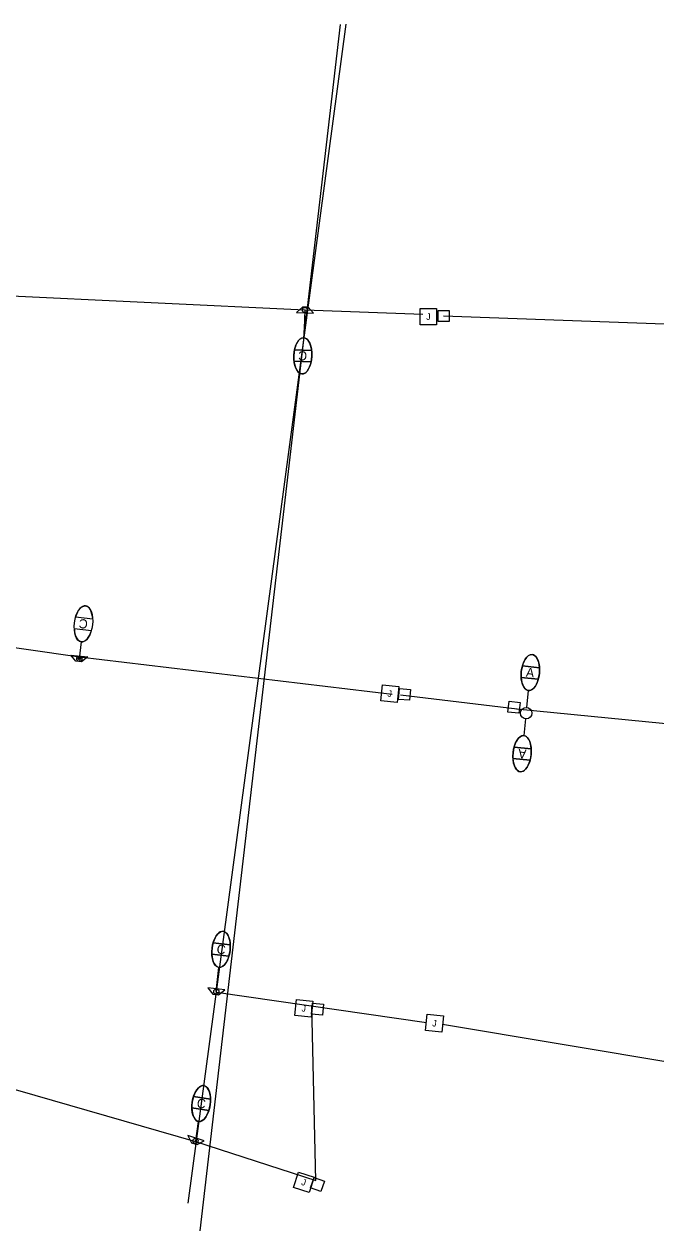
# Model space of a CAD drawing. Extents: x 915723 to 927758, y 636394 to 638609.
# Drawn here: x 926458 to 926734, y 636503 to 637030 of the extents above; entities that cross this region are included whole.
import ezdxf

# ---------------------------------------------------------------- set-up
doc = ezdxf.new("R2010")
doc.units = 0
for name, color, linetype in [('ConduitBM', 7, 'Continuous'), ('ConduitOT', 7, 'Continuous'), ('DrShaftConc', 7, 'Continuous'), ('Masonry_h', 7, 'Continuous'), ('Miscellaneous2', 7, 'Continuous'), ('PoleLight', 7, 'Continuous'), ('PullBox', 7, 'Continuous'), ('TextStructuresLabel', 7, 'Continuous')]:
    doc.layers.add(name, color=color, linetype=linetype)

msp = doc.modelspace()

# ---------------------------------------------------------------- linework, layer by layer
at = {"layer": 'ConduitBM'}
for p, q in [((926580.52, 636905.43), (926370.11, 636915.42)), ((926632.01, 636903.45), (926580.6, 636905.42)), ((926482.06, 636754), (926618.67, 636737.72)), ((926622.22, 636737.3), (926673.24, 636731.22)), ((926672.98, 636731.25), (926887.33, 636710.33)), ((926541.86, 636607.54), (926633.58, 636594.28)), ((926328.91, 636600.93), (926532.75, 636542.24)), ((926532.73, 636542.24), (926585.26, 636525.26))]:
    msp.add_line(p, q, dxfattribs=at)
msp.add_lwpolyline([(926323.33, 636771.7), (926436.28, 636760.52), (926482.05, 636754)], dxfattribs=at)
at = {"layer": 'ConduitOT'}
for p, q in [((926791.2, 636897.34), (926641.08, 636902.83)), ((926640.67, 636593.55), (926744.36, 636576.23))]:
    msp.add_line(p, q, dxfattribs=at)
msp.add_lwpolyline([(926585.26, 636525.26), (926585.26, 636525.26), (926583.47, 636601.52)], dxfattribs=at)
at = {"layer": 'DrShaftConc'}
msp.add_line((926595.9, 637030.24), (926534.59, 636503.22), dxfattribs=at)
at = {"layer": 'Masonry_h'}
for p, q in [((926598.39, 637030.33), (926529.3, 636515.3)), ((926580.43, 636902.87), (926579.95, 636892.88)), ((926580.43, 636902.87), (926579.95, 636892.88))]:
    msp.add_line(p, q, dxfattribs=at)
at = {"layer": 'Miscellaneous2'}
for p, q in [((926583.46, 636887.77), (926575.95, 636888.13)), ((926575.95, 636888.13), (926575.95, 636888.13)), ((926575.71, 636883.13), (926575.71, 636883.13)), ((926575.71, 636883.13), (926583.22, 636882.78)), ((926682.98, 636749.21), (926675.5, 636749.97)), ((926675.5, 636749.97), (926675.5, 636749.97)), ((926674.99, 636745), (926674.99, 636745)), ((926674.99, 636745), (926682.47, 636744.24)), ((926671.4, 636709.54), (926671.4, 636709.54)), ((926671.4, 636709.54), (926678.88, 636708.78)), ((926679.38, 636713.75), (926671.9, 636714.51)), ((926671.9, 636714.51), (926671.9, 636714.51)), ((926547.88, 636628.23), (926540.42, 636629.1)), ((926547.88, 636628.23), (926547.88, 636628.23)), ((926539.84, 636624.14), (926547.3, 636623.27)), ((926547.3, 636623.27), (926547.3, 636623.27)), ((926539.27, 636560.78), (926531.84, 636561.87)), ((926531.11, 636556.92), (926538.55, 636555.83)), ((926539.27, 636560.78), (926539.27, 636560.78)), ((926538.55, 636555.83), (926538.55, 636555.83))]:
    msp.add_line(p, q, dxfattribs=at)
for centre, major_axis, start_param, end_param in [((926579.58, 636885.45), (0.38, 7.91), 1.249648, 1.891946), ((926579.58, 636885.45), (0.38, 7.91), 4.391271, 5.033538), ((926579.58, 636885.45), (0.38, 7.91), 4.391241, 4.391271), ((926678.99, 636747.1), (0.8, 7.88), 1.249648, 1.891946), ((926678.99, 636747.1), (0.8, 7.88), 4.391271, 5.033538), ((926678.99, 636747.1), (0.8, 7.88), 4.391241, 4.391271), ((926675.39, 636711.65), (0.8, 7.88), 1.249648, 1.891946), ((926675.39, 636711.65), (0.8, 7.88), 4.391271, 5.033538), ((926675.39, 636711.65), (0.8, 7.88), 4.391241, 4.391271), ((926543.86, 636626.19), (-0.92, -7.87), 4.391271, 5.033538), ((926543.86, 636626.19), (-0.92, -7.87), 4.391241, 4.391271), ((926543.86, 636626.19), (-0.92, -7.87), 1.249648, 1.891946), ((926535.19, 636558.85), (-1.15, -7.84), 4.391271, 5.033538), ((926535.19, 636558.85), (-1.15, -7.84), 4.391241, 4.391271), ((926535.19, 636558.85), (-1.15, -7.84), 1.249648, 1.891946)]:
    msp.add_ellipse(centre, major_axis=major_axis, ratio=0.5, start_param=start_param, end_param=end_param, dxfattribs=at)
at = {"layer": 'PoleLight'}
for p, q in [((926580.53, 636905.44), (926579.96, 636893.36)), ((926575.95, 636888.13), (926583.46, 636887.77)), ((926583.22, 636882.78), (926575.71, 636883.13)), ((926487.78, 636770.41), (926480.32, 636771.29)), ((926479.73, 636766.32), (926487.19, 636765.44)), ((926481.95, 636753.13), (926482.82, 636760.5)), ((926675.5, 636749.97), (926682.98, 636749.21)), ((926682.47, 636744.24), (926674.99, 636745)), ((926677.44, 636731.84), (926678.19, 636739.22)), ((926676.94, 636726.91), (926676.19, 636719.53)), ((926678.88, 636708.78), (926671.4, 636709.54)), ((926671.9, 636714.51), (926679.38, 636713.75)), ((926540.42, 636629.1), (926547.88, 636628.23)), ((926547.3, 636623.27), (926539.84, 636624.14)), ((926541.71, 636607.8), (926542.95, 636618.32)), ((926531.84, 636561.87), (926539.27, 636560.78)), ((926538.55, 636555.83), (926531.11, 636556.92)), ((926532.79, 636542.5), (926534.04, 636551.02))]:
    msp.add_line(p, q, dxfattribs=at)
for points in [[(926581.93, 636906.63), (926579.43, 636906.75), (926576.81, 636904.37), (926584.3, 636904.02)], [(926482.92, 636751.73), (926480.44, 636752.01), (926478.23, 636754.76), (926485.68, 636753.95)], [(926482.92, 636751.73), (926480.44, 636752.01), (926478.23, 636754.76), (926485.68, 636753.95)], [(926540.32, 636606.6), (926542.8, 636606.32), (926545.57, 636608.51), (926538.13, 636609.37)], [(926531.02, 636541.7), (926533.41, 636540.96), (926536.54, 636542.58), (926529.39, 636544.84)]]:
    msp.add_lwpolyline(points, close=True, dxfattribs=at)
for centre, radius in [((926580.53, 636905.44), 1.14), ((926481.95, 636753.13), 1.14), ((926481.95, 636753.13), 0.569), ((926677.19, 636729.37), 2.48), ((926677.19, 636729.37), 2.48), ((926541.78, 636607.71), 1.14), ((926532.66, 636542.52), 1.14)]:
    msp.add_circle(centre, radius, dxfattribs=at)
for centre, major_axis in [((926579.58, 636885.45), (0.38, 7.91)), ((926483.75, 636768.36), (-0.93, -7.87)), ((926678.99, 636747.1), (0.8, 7.88)), ((926675.39, 636711.65), (0.8, 7.88)), ((926543.86, 636626.19), (-0.92, -7.87)), ((926535.19, 636558.85), (-1.15, -7.84))]:
    msp.add_ellipse(centre, major_axis=major_axis, ratio=0.5, dxfattribs=at)
for centre, major_axis, start_param, end_param in [((926579.58, 636885.45), (0.38, 7.91), 0.847605, 1.249648), ((926579.58, 636885.45), (0.38, 7.91), 0, 0.847605), ((926579.58, 636885.45), (0.38, 7.91), 5.033538, 6.283185), ((926579.58, 636885.45), (0.38, 7.91), 1.891945, 4.391241), ((926483.75, 636768.36), (-0.93, -7.87), 1.891945, 4.39124), ((926483.75, 636768.36), (-0.93, -7.87), 5.033537, 5.43558), ((926483.75, 636768.36), (-0.93, -7.87), 5.43558, 6.283185), ((926483.75, 636768.36), (-0.93, -7.87), 0, 1.249648), ((926678.99, 636747.1), (0.8, 7.88), 0.847605, 1.249648), ((926678.99, 636747.1), (0.8, 7.88), 0, 0.847605), ((926678.99, 636747.1), (0.8, 7.88), 5.033538, 6.283185), ((926678.99, 636747.1), (0.8, 7.88), 1.891945, 4.391241), ((926675.39, 636711.65), (0.8, 7.88), 0.847605, 1.249648), ((926675.39, 636711.65), (0.8, 7.88), 0, 0.847605), ((926675.39, 636711.65), (0.8, 7.88), 5.033538, 6.283185), ((926675.39, 636711.65), (0.8, 7.88), 1.891945, 4.391241), ((926543.86, 636626.19), (-0.92, -7.87), 1.891945, 4.391241), ((926543.86, 636626.19), (-0.92, -7.87), 5.033538, 6.283185), ((926543.86, 636626.19), (-0.92, -7.87), 0, 0.847605), ((926543.86, 636626.19), (-0.92, -7.87), 0.847605, 1.249648), ((926535.19, 636558.85), (-1.15, -7.84), 1.891945, 4.391241), ((926535.19, 636558.85), (-1.15, -7.84), 5.033538, 6.283185), ((926535.19, 636558.85), (-1.15, -7.84), 0, 0.847605), ((926535.19, 636558.85), (-1.15, -7.84), 0.847605, 1.249648)]:
    msp.add_ellipse(centre, major_axis=major_axis, ratio=0.5, start_param=start_param, end_param=end_param, dxfattribs=at)
at = {"layer": 'PullBox'}
for p, q in [((926630.9, 636906.14), (926638.02, 636906.14)), ((926630.9, 636899.02), (926630.9, 636906.14)), ((926638.02, 636906.14), (926638.02, 636899.02)), ((926638.68, 636900.43), (926638.68, 636905.23)), ((926638.68, 636905.23), (926643.48, 636905.23)), ((926643.48, 636905.23), (926643.48, 636900.43)), ((926643.48, 636900.43), (926638.68, 636900.43)), ((926638.02, 636899.02), (926630.9, 636899.02)), ((926613.68, 636734.7), (926614.41, 636741.79)), ((926614.41, 636741.79), (926621.49, 636741.06)), ((926621.49, 636741.06), (926620.76, 636733.97)), ((926621.45, 636735.38), (926621.86, 636740.17)), ((926621.86, 636740.17), (926626.65, 636739.76)), ((926626.65, 636739.76), (926626.24, 636734.97)), ((926620.76, 636733.97), (926613.68, 636734.7)), ((926626.24, 636734.97), (926621.45, 636735.38)), ((926669.19, 636729.84), (926669.74, 636734.61)), ((926669.74, 636734.61), (926674.51, 636734.06)), ((926674.51, 636734.06), (926673.96, 636729.29)), ((926673.96, 636729.29), (926669.19, 636729.84)), ((926576.12, 636597.23), (926576.85, 636604.32)), ((926576.85, 636604.32), (926583.93, 636603.59)), ((926583.93, 636603.59), (926583.2, 636596.5)), ((926583.42, 636597.88), (926583.82, 636602.67)), ((926583.82, 636602.67), (926588.61, 636602.26)), ((926588.61, 636602.26), (926588.2, 636597.47)), ((926583.2, 636596.5), (926576.12, 636597.23)), ((926588.2, 636597.47), (926583.42, 636597.88)), ((926633.22, 636590.73), (926633.95, 636597.82)), ((926633.95, 636597.82), (926641.04, 636597.09)), ((926641.04, 636597.09), (926640.31, 636590)), ((926640.31, 636590), (926633.22, 636590.73)), ((926575.56, 636522.14), (926577.77, 636528.91)), ((926577.77, 636528.91), (926584.54, 636526.71)), ((926584.54, 636526.71), (926582.34, 636519.93)), ((926582.96, 636521.97), (926584.49, 636526.53)), ((926584.49, 636526.53), (926589.04, 636524.99)), ((926589.04, 636524.99), (926587.51, 636520.44)), ((926582.34, 636519.93), (926575.56, 636522.14)), ((926587.51, 636520.44), (926582.96, 636521.97))]:
    msp.add_line(p, q, dxfattribs=at)

# ---------------------------------------------------------------- texts
at = {"layer": 'ConduitOT'}
for rotation, p in [(0, (926633.49, 636901.16)), (354.1293, (926616.48, 636736.56)), (354.1293, (926578.92, 636599.09)), (354.1293, (926636.02, 636592.59)), (341.98, (926578.69, 636523.37))]:
    msp.add_text('J', height=2.85, rotation=rotation, dxfattribs=at).set_placement(p)
at = {"layer": 'TextStructuresLabel'}
for s, rotation, p in [('C', 177.277, (926581.55, 636887.36)), ('C', 173.2504, (926485.85, 636770.12)), ('A', 354.2099, (926676.93, 636745.3)), ('A', 174.2099, (926677.45, 636713.45)), ('C', 353.3649, (926541.77, 636624.42)), ('C', 351.638, (926533.05, 636557.15))]:
    msp.add_text(s, height=4, rotation=rotation, dxfattribs=at).set_placement(p)

doc.saveas('drawing.dxf')
